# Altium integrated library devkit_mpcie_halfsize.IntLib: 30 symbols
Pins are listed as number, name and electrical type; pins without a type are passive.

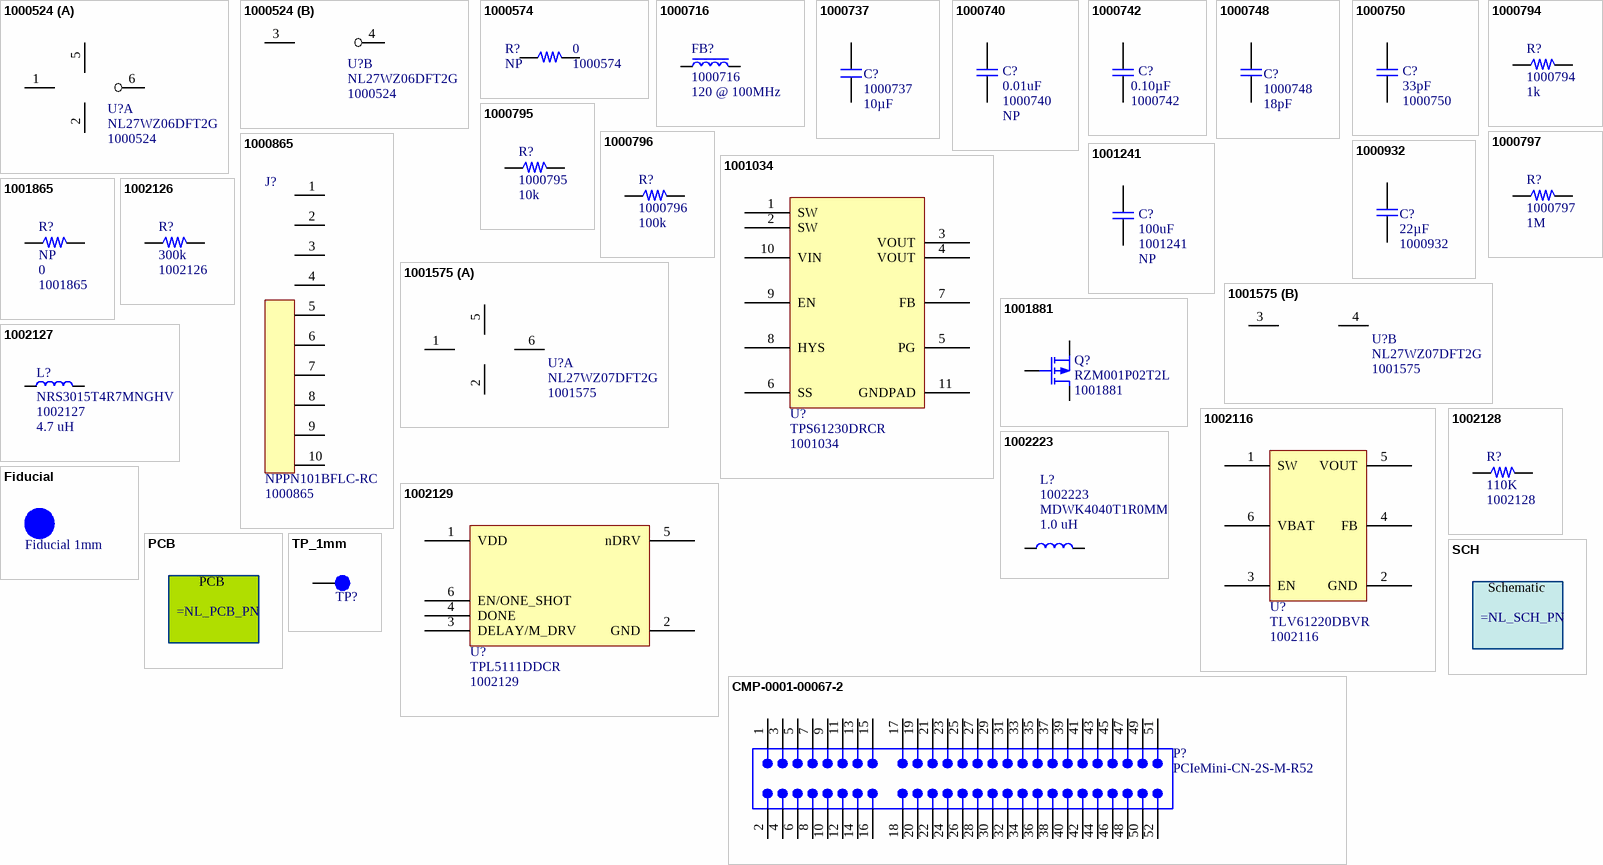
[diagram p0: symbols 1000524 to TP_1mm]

## 1000524
designator U?, comment Part_Number: 1000524  (hidden comment: NL27WZ06DFT2G)
IC, Inverter, Dual, Open Drain,1.65-5.5V, SC88; Manufacturer1: ON Semiconductor; Item_Phase: Production; Mounting_Type: Surface Mount; Operating_Temperature: -55°C ~ 125°C; Voltage_Supply_Max: 5.5V; Voltage_Supply_Min: 1.65V
footprint SOT65P210X110-6N (SOT23, 6-Leads, Body 2.00x2.10mm, Pitch 0.65mm, IPC Medium Density)
part A pins: 1, 2 GND, 5 VCC, 6
part B pins: 3, 4

## 1000574
designator R?, comment Population: NP  Part_Number: 1000574  (hidden comment: 0)
Resistor, 0, 1/10W, 0402; Manufacturer1: Panasonic Electronic Components; Manufacturer_Part_Number1: ERJ-2GE0R00X; Item_Phase: Production; Mounting_Type: Surface Mount; Number_of_Terminations: 2; Operating_Temperature: -55°C ~ 155°C; Power: 0.1W, 1/10W; Resistor_Package: 0402 (1005 Metric); Tolerance: Jumper
footprint 0402
pins: 1, 2

## 1000716
designator FB?, comment Part_Number: 1000716  Resistance_at_Frequency: 120 @ 100MHz  (hidden comment: PE-0603PFB121ST)
Ferrite Bead, 120 ohm @100mHz, 2A, 50mOHM-DC, 0603; Manufacturer_Part_Number1: BLM18PG121SZ1D; Manufacturer1: Murata Electronics North America; Item_Phase: Production; Mounting_Type: Surface Mount; Resistance_DC: 50 mOhm
footprint 0603
pins: 1, 2

## 1000737
designator C?, comment Part_Number: 1000737  Capacitance: 10µF  (hidden comment: C, 10 uF, 10V, X5R, 20%, 0402 CER)
Capacitor, 10 uF, 10V, 20%, X5R, 0402; Manufacturer1: Venkel LTD.; Manufacturer_Part_Number1: C0402X5R100-106MNP; Item_Phase: Production; Capacitor_Type: Ceramic; Mounting_Type: Surface Mount; Operating_Temperature: -55°C ~ 85°C; Thickness_Max: 0.035" (0.90mm)
footprint 0402
pins: 1, 2

## 1000740
designator C?, comment Population: NP  Part_Number: 1000740  Capacitance: 0.01uF  (hidden comment: CAPACITOR)
Capacitor, 0.01 uF, 25V, 5%, X7R, 0402
footprint 0402
pins: 1, 2

## 1000742
designator C?  Capacitance: 0.10µF  Part_Number: 1000742
Capacitor, 0.1 uF, 16V, 10%, X7R, 0402; Manufacturer1: Kemet; Manufacturer_Part_Number1: C0402C104K4RALTU; Item_Phase: Production; Capacitor_Type: Ceramic; Mounting_Type: Surface Mount; Operating_Temperature: -55°C ~ 125°C; Thickness_Max: 0.022" (0.55mm)
footprint 0402
pins: 1, 2

## 1000748
designator C?, comment Part_Number: 1000748  Capacitance: 18pF  (hidden comment: C, 18 pF, 50V, 5%, C0G/NPO, 0402 CER)
Capacitor, 18 pF, 50V, 5%, C0G/NPO, 0402; Manufacturer1: Samsung Electro-Mechanics America, Inc; Manufacturer_Part_Number1: CL05C180JB5NNNC; Item_Phase: Production; Capacitor_Type: Ceramic; Mounting_Type: Surface Mount; Operating_Temperature: -55°C ~ 125°C; Temperature_Coefficient: C0G, NP0; Thickness_Max: 0.022" (0.55mm)
footprint 0402
pins: 1, 2

## 1000750
designator C?, comment Part_Number: 1000750  Capacitance: 33pF  (hidden comment: C, 33 pF, 50V, 5%, C0G/NP0, 0402 CER)
Capacitor, 33 pF, 50V, 5%, C0G/NP0, 0402; Manufacturer1: Kemet; Manufacturer_Part_Number1: C0402C330J5GACTU; Item_Phase: Production; Capacitor_Type: Ceramic; Mounting_Type: Surface Mount; Operating_Temperature: -55°C ~ 125°C; Temperature_Coefficient: C0G, NP0; Thickness_Max: 0.022" (0.55mm)
footprint 0402
pins: 1, 2

## 1000794
designator R?, comment Part_Number: 1000794  Resistance_Ohms: 1k  (hidden comment: R, 1K, 1%, 1/16W, 0402)
Resistor, 1K, 1%, 1/16W, 0402; Manufacturer1: Bourns Inc; Manufacturer_Part_Number1: CR0402-FX-1001GLF; Item_Phase: Production; Mounting_Type: Surface Mount; Number_of_Terminations: 2; Operating_Temperature: -55°C ~ 155°C; Power: 0.063W, 1/16W; Resistor_Package: 0402 (1005 Metric); Temperature_Coefficient: ±100ppm/°C
footprint 0402
pins: 1, 2

## 1000795
designator R?, comment Part_Number: 1000795  Resistance_Ohms: 10k  (hidden comment: R, 10K, 1%, 1/16W,  0402)
Resistor, 10K, 1%, 1/16W, 0402; Manufacturer1: Bourns Inc; Manufacturer_Part_Number1: CR0402-FX-1002GLF; Item_Phase: Production; Mounting_Type: Surface Mount; Number_of_Terminations: 2; Operating_Temperature: -55°C ~ 155°C; Power: 0.063W, 1/16W; Resistor_Package: 0402 (1005 Metric); Temperature_Coefficient: ±100ppm/°C
footprint 0402
pins: 1, 2

## 1000796
designator R?, comment Part_Number: 1000796  Resistance_Ohms: 100k  (hidden comment: R, 100K, 1%, 1/16W,  0402)
Resistor, 100K, 1%, 1/16W, 0402; Manufacturer1: Bourns Inc; Manufacturer_Part_Number1: CR0402-FX-1003GLF; Item_Phase: Production; Mounting_Type: Surface Mount; Number_of_Terminations: 2; Operating_Temperature: -55°C ~ 155°C; Power: 0.063W, 1/16W; Resistor_Package: 0402 (1005 Metric); Temperature_Coefficient: ±100ppm/°C
footprint 0402
pins: 1, 2

## 1000797
designator R?, comment Part_Number: 1000797  Resistance_Ohms: 1M  (hidden comment: R, 1M, 1%, 1/16W, 0402)
Resistor, 1M, 1%, 1/16W, 0402; Manufacturer1: Bourns Inc; Manufacturer_Part_Number1: CR0402-FX-1004GLF; Item_Phase: Production; Mounting_Type: Surface Mount; Number_of_Terminations: 2; Operating_Temperature: -55°C ~ 155°C; Power: 0.063W, 1/16W; Resistor_Package: 0402 (1005 Metric); Temperature_Coefficient: ±100ppm/°C
footprint 0402
pins: 1, 2

## 1000865
designator J?  Manufacturer_Part_Number1: NPPN101BFLC-RC  (hidden comment: 1000865)
Connector, Female, 2.00mm, 10x1, SMD, Left Oriented; Manufacturer1: Sullins Connector Solutions; Item_Phase: Production; Connector_Type: Header; Contact_Finish: Gold; Contact_Type: Female Socket; Current_Rating: 2A; Fastening_Type: Push-Pull; Header_Orientation: Vertical; Insertion_Removal_Method: Push In / Pull Out; Mounting_Type: Surface Mount; Number_of_Pins: 10; Number_of_Rows: 1; Operating_Temperature: -40°C ~ 105°C; Pitch: 0.079" (2.00mm); Voltage_Rating: 150V
footprint NPPN101BFLC-RC (Skywire Footprint with surfacemount pads)
pins: 1, 2, 3, 4, 5, 6, 7, 8, 9, 10

## 1000932
designator C?  Capacitance: 22µF  Part_Number: 1000932
Capacitor, 22 uF, 25V, 20%, X5R, 0603; Manufacturer1: TDK Corporation; Manufacturer_Part_Number1: C1608X5R1A226M080AC; Item_Phase: Production; Capacitor_Type: Ceramic; Mounting_Type: Surface Mount; Operating_Temperature: -55°C ~ 85°C; Thickness_Max: 0.035" (0.90mm); Voltage_Rating: 10V
footprint 0603
pins: 1, 2

## 1001034
designator U?, comment Part_Number: 1001034  (hidden comment: TPS61230DRCR)
IC, Boost, ADJ, 2.5V-5.5V, 2.1A, VSON; Manufacturer1: Texas Instruments; Item_Phase: Production; Mounting_Type: Surface Mount; Operating_Temperature: -40°C ~ 125°C; Output_Type: Adjustable
footprint PSON50P300X100_HS-11N (PSON, 10-Leads, Body 3.00x3.00mm, Pitch 0.50mm, Thermal Pad 2.15x1.60mm, IPC Medium Density)
pins: 1 SW, 2 SW, 3 VOUT, 4 VOUT, 5 PG, 6 SS, 7 FB, 8 HYS, 9 EN, 10 VIN, 11 GNDPAD

## 1001241
designator C?  Population: NP  Capacitance: 100uF  (hidden comment: 1001241)
Capacitor. 100uF, 10V, 20%, X5R, 1210; Manufacturer1: Taiyo Yuden; Manufacturer_Part_Number1: LMK325BJ107MM-T; Tolerance: +/- 20%; Item_Phase: Production; Capacitor_Type: Ceramic; Mounting_Type: Surface Mount; Operating_Temperature: -55C ~ +85C; Thickness_Max: 0.106 (2.70mm)"
footprint CAPC3225X25N_1210 (Chip Capacitor, 2-Leads, 1210)
pins: 1, 2

## 1001575
designator U?, comment Part_Number: 1001575  (hidden comment: NL27WZ07DFT2G)
IC, Buffer, Dual, Open Drain,1.65-5.5V, SC88; Manufacturer1: ON Semiconductor; Item_Phase: Preliminary; IC_Function: Logic; Mounting_Type: Surface Mount; Operating_Temperature: -55°C ~ 125°C; Voltage_Supply_Max: 5.5V; Voltage_Supply_Min: 1.65V
footprint SOT65P210X110-6N (SOT23, 6-Leads, Body 2.00x2.10mm, Pitch 0.65mm, IPC Medium Density)
part A pins: 1, 2 GND, 5 VCC, 6
part B pins: 3, 4

## 1001865
designator R?, comment Population: NP  Resistance_Ohms: 0  Part_Number: 1001865  (hidden comment: RESISTOR)
Resistor, 0, 1/16W, 0402; Manufacturer1: Bourns Inc; Manufacturer_Part_Number1: CR0402-J/-000GLF; Item_Phase: Production; Mounting_Type: Surface Mount; Number_of_Terminations: 2; Operating_Temperature: -55C ~ 155C; Resistor_Package: 0402 (1005 Metric)
footprint 0402
pins: 1, 2

## 1001881
designator Q?, comment Manufacturer_Part_Number1: RZM001P02T2L  Part_Number: 1001881  (hidden comment: MOSFET_P)
Transistor, MOSFET, P-CH, 20V, 0.100A, SOT-723; Manufacturer1: Rohm Semiconductor; Item_Phase: Production; Mounting_Type: Surface Mount; Operating_Temperature: -55°C ~ 150°C; Transistor_Type: PCH - FET
footprint SOT-723
pins: 1 G, 2 S, 3 D

## 1002116
designator U?, comment Manufacturer_Part_Number1: TLV61220DBVR  Part_Number: 1002116  (hidden comment: TLV61220)
IC, BOOST, ADJ, 1.8V-5.5V, 0.22A, SOT-23-6; Manufacturer1: Texas Instruments; Item_Phase: Production; Mounting_Type: Surface Mount; Operating_Temperature: -40C to +85C; Voltage_Supply_Max: 5.5V; Voltage_Supply_Min: 0.7V; Voltage_Supply_Typical: 3.3
footprint SOT95P280X110-6N (SOT23, 6-Leads, Body 2.90x2.80mm, Pitch 0.95mm, IPC Medium Density)
pins: 1 SW, 2 GND, 3 EN, 4 FB, 5 VOUT, 6 VBAT

## 1002126
designator R?, comment Resistance_Ohms: 300k  Part_Number: 1002126  (hidden comment: RESISTOR)
Resistor, 300K, 1%, 1/16W, 0402; Manufacturer1: Stackpole Electronics Inc; Manufacturer_Part_Number1: RMCF0402FT300k; Item_Phase: Production; Mounting_Type: Surface Mount; Operating_Temperature: -55C to 155C; Resistor_Package: 0402 (1005 Metric); Temperature_Coefficient: ±100ppm/°C
footprint 0402
pins: 1, 2

## 1002127
designator L?, comment Manufacturer_Part_Number1: NRS3015T4R7MNGHV  Part_Number: 1002127  Inductance: 4.7 uH  (hidden comment: INDUCTOR)
Inductor, 4.7 uH, 1.04 A, 20%, 144 mOHM, Shielded, 3X3mm; Manufacturer1: Taiyo Yuden; Item_Phase: Production; Current_Saturation: 1.02A; Current_Rating: 1.04A; Mounting_Type: Surface Mount; Operating_Temperature: -40C to +125C; Inductor_Type: Wirewound
footprint NRS3015
pins: 1, 2

## 1002128
designator R?, comment Resistance_Ohms: 110K  Part_Number: 1002128  (hidden comment: RESISTOR)
Resistor, 110K, 1%, 1/16W, 0402; Manufacturer1: Yageo; Manufacturer_Part_Number1: RC0402FR-07110KL; Item_Phase: Production; Mounting_Type: Surface Mount; Operating_Temperature: -55C to +125C; Resistor_Package: 0402 (1005 Metric); Temperature_Coefficient: ±100ppm/°C
footprint 0402
pins: 1, 2

## 1002129
designator U?, comment Manufacturer_Part_Number1: TPL5111DDCR  Part_Number: 1002129  (hidden comment: TPL5111)
IC, Timer, 0.1-7200s, 1%, 1.8V-5.5V, TSOT-23-6; Manufacturer1: Texas Instruments; Item_Phase: Production; IC_Function: Logic; Mounting_Type: Surface Mount; Operating_Temperature: -40C to +105C; Voltage_Supply_Max: 5.5V; Voltage_Supply_Min: 1.8V; Voltage_Supply_Typical: 3.3V
footprint SOT95P280X110-6N
pins: 1 VDD, 2 GND, 3 DELAY/M_DRV, 4 DONE, 5 nDRV, 6 EN/ONE_SHOT

## 1002223
designator L?, comment Manufacturer_Part_Number1: MDWK4040T1R0MM  Part_Number: 1002223  Inductance: 1.0 uH  (hidden comment: INDUCTOR)
Inductor, 1 uH, 5.1A, 20%, 27 mOhm, Shielded, 4.00x4.00x2.00mm; Manufacturer1: Taiyo Yuden; Item_Phase: Production; Current_Saturation: 7A; DC_Resistance: 27 mOhm; Mounting_Type: Surface Mount; Operating_Temperature: -40C to +125C; Inductor_Type: Wirewound
footprint MDWK4040
pins: 1, 2

## CMP-0001-00067-2
designator P?, comment PCIeMini-CN-2S-M-R52  (no BOM)
Golden finger, PCIeMini, Dual, Staggered, Pitch 0.8mm, 52-Position; Mating Connector: Tyco-292443-1; Package Version: rev1.2, Oct-2007
footprint PCIeMini-GF-2D-800-1K-S52 (Golden finger, PCIeMini, Dual, Staggered, Pitch 0.8mm, 52-Position)
pins: 1, 2, 3, 4, 5, 6, 7, 8, 9, 10, 11, 12, 13, 14, 15, 16, 17, 18, 19, 20, 21, 22, 23, 24, 25, 26, 27, 28, 29, 30, 31, 32, 33, 34, 35, 36, 37, 38, 39, 40, 41, 42, 43, 44, 45, 46, 47, 48, 49, 50, 51, 52

## Fiducial
designator Fiducial?, comment Fiducial 1mm  (no BOM)
Population: NP
footprint Fiducial 1mm

## PCB
designator PCB?  (value not drawn)  (mechanical)
PCB Part Number

## SCH
designator SCH?  (value not drawn)  (mechanical)
Schematic Part Number

## TP_1mm
designator TP?, comment Test Point 1mm  (value not drawn)  (no BOM)
TEST POINT, SMD 1mm; Population: NP
footprint Test_Point 1mm
pins: 1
